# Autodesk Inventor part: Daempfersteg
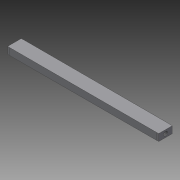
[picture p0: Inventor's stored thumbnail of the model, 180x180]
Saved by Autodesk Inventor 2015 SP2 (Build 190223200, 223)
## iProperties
Created: 2012-07
Part Number: Daempfersteg
Material: Allgemein
Document SubType Name: Modeling
Designer: rYan
Density: 1 g/cm^3
Mass: 2.66184 g
Surface Area: 25.5663 cm^2
Volume: 2.66184 cm^3
Appearance: Vorgabe
Author: rYan
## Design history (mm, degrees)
sketch "Skizze1"
  geometry: L1 (44, -4)-(44, 4); L2 (-44, 4)-(-44, -4); L3 (0, 5.6)-(0, -5.6) reference; L4 (-61.6, 0)-(61.6, 0) reference; L5 (-44, -4)-(44, -4); L6 (44, 4)-(-44, 4); 1 further point
  constraints: 8 end point, 2 parallel, 2 symmetric about line, 1 horizontal, 1 perpendicular, 1 other
  dimensions: "d146" = 88 distance between parallel lines of L2 L1; "d147" = 8 distance of L1.start L1.end
extrude "Extrusion1" new body sketch "Skizze1" distance "d3" = 4; taper "d4" = 0 deg
sketch "Skizze9"
  geometry: L1 (0, 0)-(0, 8) reference; L2 (-4, 0)-(-4, 8) reference; L3 (-4, 4)-(0, 4); L4 (0, 8)-(-4, 8) reference; L5 (0, 0)-(-4, 0) reference; 3 further points
  constraints: 3 midpoint, 2 coincident, 2 end point
hole "Bohrung4" sketch "Skizze9" at (-2, 4) diameter "d42" = 2.459; stored, may be unused: countersink angle "d46" = 90 deg, drill point angle "d48" = 118 deg; dims "d43" = 5, "d44" = 4, "d45" = 2, "d47" = 6
node "Bohrungsspiegel"
chamfer "Fase1" distance "d107" = 1; stored, may be unused: second distance "d108" = 2, angle "d109" = 5 deg
mirror "Spiegeln3"
chamfer "Fase10" distance "d141" = 1; stored, may be unused: second distance "d142" = 2, angle "d143" = 5 deg
node "Volumenkörper1"
node "Projizierte Kontur4"
other parameters: "d104" = 8
